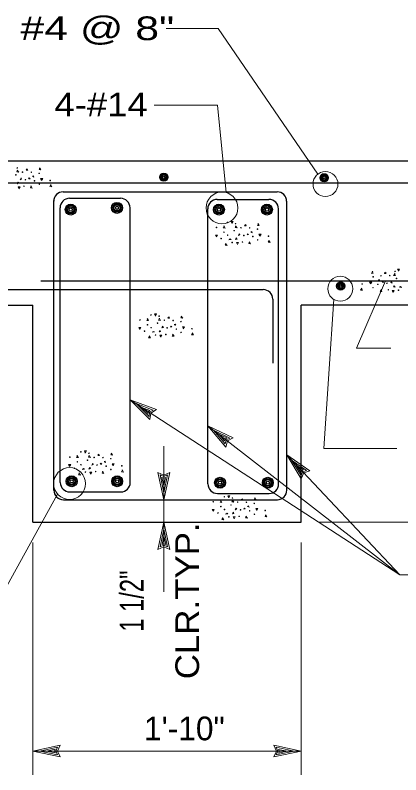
# Model space of a CAD drawing. Extents: x -28.1 to 13.9, y -16.1 to 13.9.
# Drawn here: x -17.081 to -15.047, y -12.729 to -8.723 of the extents above; entities that cross this region are included whole.
import ezdxf
from ezdxf.enums import TextEntityAlignment as Align

# ---------------------------------------------------------------- set-up
doc = ezdxf.new("R2010")
doc.units = 0
doc.header["$LTSCALE"] = 0.05
doc.layers.add('1', color=7, linetype='Continuous', lineweight=13)
doc.layers.add('2', color=7, linetype='Continuous', lineweight=13)

msp = doc.modelspace()

# ---------------------------------------------------------------- linework, layer by layer
at = {"layer": '1', "lineweight": 25}
for p, q in [((-18.82104, -9.49131), (-13.73804, -9.49131)), ((-18.82204, -9.60631), (-13.73904, -9.60631)), ((-16.82804, -9.65431), (-15.69904, -9.65431)), ((-16.79404, -9.68831), (-16.52504, -9.68831)), ((-16.01504, -9.69431), (-15.74204, -9.69431)), ((-16.87704, -11.22831), (-16.87704, -9.70031)), ((-15.64804, -11.22831), (-15.64804, -9.70431)), ((-16.84304, -11.18731), (-16.84304, -9.73831)), ((-16.47404, -11.18731), (-16.47404, -9.73831)), ((-16.06404, -11.19531), (-16.06404, -9.74431)), ((-15.69104, -11.19531), (-15.69104, -9.74431)), ((-16.94504, -10.12331), (-13.73804, -10.12331)), ((-18.81504, -10.17031), (-15.77204, -10.17031)), ((-18.82204, -10.25231), (-16.98804, -10.25231)), ((-16.98804, -11.39631), (-16.98804, -10.25231)), ((-15.72204, -10.22031), (-15.72204, -10.55831)), ((-15.57304, -11.39631), (-15.57304, -10.25231)), ((-13.73804, -10.25231), (-15.57304, -10.25231)), ((-16.79304, -11.23731), (-16.52404, -11.23731)), ((-16.01404, -11.24531), (-15.74104, -11.24531)), ((-16.82704, -11.27831), (-15.69804, -11.27831)), ((-16.98804, -11.39631), (-15.57304, -11.39631))]:
    msp.add_line(p, q, dxfattribs=at)
at = {"layer": '1'}
for p, q in [((-15.28104, -10.47831), (-15.12804, -10.12331)), ((-15.45204, -11.00831), (-15.40004, -10.22131)), ((-15.28104, -10.47831), (-15.10004, -10.47831)), ((-15.05104, -11.67531), (-16.47404, -10.75131)), ((-16.47404, -10.75131), (-16.33604, -10.80331)), ((-16.47404, -10.75131), (-16.37004, -10.85531)), ((-16.44304, -10.77131), (-16.35304, -10.80631)), ((-16.44304, -10.77131), (-16.37504, -10.83931)), ((-16.41304, -10.79131), (-16.38004, -10.82331)), ((-16.41304, -10.79131), (-16.37004, -10.80731)), ((-16.37804, -10.81331), (-16.38004, -10.82331)), ((-16.37004, -10.80731), (-16.37804, -10.81331)), ((-16.37204, -10.81731), (-16.37504, -10.83931)), ((-16.35304, -10.80631), (-16.37204, -10.81731)), ((-15.05104, -11.67531), (-16.06404, -10.88831)), ((-16.06404, -10.88831), (-15.93104, -10.95231)), ((-16.06404, -10.88831), (-15.96904, -11.00131)), ((-16.03504, -10.91131), (-15.94804, -10.95331)), ((-16.03504, -10.91131), (-15.97304, -10.98431)), ((-16.00604, -10.93331), (-15.97604, -10.96831)), ((-16.00604, -10.93331), (-15.96504, -10.95231)), ((-15.97404, -10.95831), (-15.97604, -10.96831)), ((-15.96504, -10.95231), (-15.97404, -10.95831)), ((-15.96804, -10.96331), (-15.97304, -10.98431)), ((-15.94804, -10.95331), (-15.96804, -10.96331)), ((-15.45204, -11.00831), (-15.06804, -11.00831)), ((-15.05104, -11.67531), (-15.64804, -11.04231)), ((-15.64804, -11.04231), (-15.52704, -11.12531)), ((-15.64804, -11.04231), (-15.57204, -11.16831)), ((-15.62304, -11.06931), (-15.54404, -11.12431)), ((-15.62304, -11.06931), (-15.57304, -11.15131)), ((-15.59804, -11.09531), (-15.57404, -11.13431)), ((-15.59804, -11.09531), (-15.56004, -11.12131)), ((-16.29704, -11.27831), (-16.32804, -11.13431)), ((-16.29704, -11.27831), (-16.26604, -11.13431)), ((-15.57004, -11.12531), (-15.57404, -11.13431)), ((-15.56404, -11.13131), (-15.57304, -11.15131)), ((-15.56004, -11.12131), (-15.57004, -11.12531)), ((-15.54404, -11.12431), (-15.56404, -11.13131)), ((-16.29704, -11.24131), (-16.31704, -11.14731)), ((-16.31704, -11.14731), (-16.29704, -11.15631)), ((-16.29704, -11.20531), (-16.30704, -11.16031)), ((-16.30704, -11.16031), (-16.29704, -11.16431)), ((-16.29704, -11.24131), (-16.27704, -11.14731)), ((-16.29704, -11.15631), (-16.27704, -11.14731)), ((-16.29704, -11.20531), (-16.28804, -11.16031)), ((-16.29704, -11.16431), (-16.28804, -11.16031)), ((-17.20904, -11.88431), (-16.85704, -11.24831)), ((-16.29704, -11.39631), (-16.32804, -11.54031)), ((-16.29704, -11.39631), (-16.26604, -11.54031)), ((-15.47804, -11.39631), (-11.56504, -11.39631)), ((-16.29704, -11.43331), (-16.31704, -11.52731)), ((-16.29704, -11.43331), (-16.27704, -11.52731)), ((-16.29704, -11.46931), (-16.30604, -11.51431)), ((-16.29704, -11.46931), (-16.28704, -11.51431)), ((-16.98804, -11.50431), (-16.98804, -12.72931)), ((-16.29704, -11.51831), (-16.31704, -11.52731)), ((-16.29704, -11.51031), (-16.30604, -11.51431)), ((-16.28704, -11.51431), (-16.29704, -11.51031)), ((-16.27704, -11.52731), (-16.29704, -11.51831)), ((-15.57304, -11.50431), (-15.57304, -12.72931)), ((-15.05104, -11.67531), (-14.66204, -11.67531)), ((-16.98804, -12.60431), (-16.84404, -12.57331)), ((-15.57304, -12.60431), (-15.71704, -12.57331)), ((-16.98804, -12.60431), (-15.57304, -12.60431)), ((-16.98804, -12.60431), (-16.84404, -12.63531)), ((-16.95104, -12.60431), (-16.85704, -12.58431)), ((-16.95104, -12.60431), (-16.85704, -12.62431)), ((-16.91504, -12.60431), (-16.87004, -12.59431)), ((-16.91504, -12.60431), (-16.87004, -12.61331)), ((-16.87004, -12.59431), (-16.87404, -12.60431)), ((-16.87404, -12.60431), (-16.87004, -12.61331)), ((-16.85704, -12.58431), (-16.86604, -12.60431)), ((-16.86604, -12.60431), (-16.85704, -12.62431)), ((-15.57304, -12.60431), (-15.71704, -12.63531)), ((-15.61004, -12.60431), (-15.70404, -12.58431)), ((-15.69504, -12.60431), (-15.70404, -12.58431)), ((-15.61004, -12.60431), (-15.70404, -12.62431)), ((-15.70404, -12.62431), (-15.69504, -12.60431)), ((-15.64604, -12.60431), (-15.69104, -12.59531)), ((-15.68704, -12.60431), (-15.69104, -12.59531)), ((-15.64604, -12.60431), (-15.69104, -12.61431)), ((-15.69104, -12.61431), (-15.68704, -12.60431))]:
    msp.add_line(p, q, dxfattribs=at)
for points in [[(-16.28404, -8.79231), (-16.01104, -8.79231), (-15.48504, -9.56131)], [(-16.34804, -9.19731), (-16.01404, -9.19731), (-15.96804, -9.65831)], [(-16.33604, -10.80331), (-16.36504, -10.82231), (-16.37004, -10.85531)], [(-15.93104, -10.95231), (-15.96104, -10.96831), (-15.96904, -11.00131)], [(-16.29704, -11.76431), (-16.29704, -11.39631), (-16.29704, -11.27831), (-16.29704, -10.99531)], [(-16.32804, -11.13431), (-16.29704, -11.14831), (-16.26604, -11.13431)], [(-15.52704, -11.12531), (-15.55904, -11.13731), (-15.57204, -11.16831)], [(-16.26604, -11.54031), (-16.29704, -11.52631), (-16.32804, -11.54031)], [(-16.84404, -12.57331), (-16.85804, -12.60431), (-16.84404, -12.63531)], [(-15.71704, -12.63531), (-15.70304, -12.60431), (-15.71704, -12.57331)]]:
    msp.add_lwpolyline(points, dxfattribs=at)
at = {"layer": '1', "lineweight": 25}
for centre, radius in [((-16.29699, -9.57723), 0.02168), ((-16.29699, -9.57723), 0.01681), ((-16.29699, -9.57723), 0.01233), ((-16.29699, -9.57723), 0.00623), ((-15.45099, -9.58023), 0.02168), ((-15.45099, -9.58023), 0.01681), ((-15.45099, -9.58023), 0.01233), ((-15.45099, -9.58023), 0.00623), ((-16.7881, -9.74788), 0.02891), ((-16.7881, -9.74788), 0.02242), ((-16.7881, -9.74788), 0.01644), ((-16.5441, -9.73888), 0.02891), ((-16.5441, -9.73888), 0.02242), ((-16.5441, -9.73888), 0.01644), ((-16.5441, -9.73888), 0.0083), ((-16.0061, -9.74788), 0.02891), ((-16.0061, -9.74788), 0.02242), ((-16.0061, -9.74788), 0.01644), ((-15.7531, -9.74788), 0.02891), ((-15.7531, -9.74788), 0.02242), ((-15.7531, -9.74788), 0.01644), ((-16.7881, -9.74788), 0.0083), ((-16.0061, -9.74788), 0.0083), ((-15.7531, -9.74788), 0.0083), ((-15.36399, -10.15123), 0.02168), ((-15.36399, -10.15123), 0.01681), ((-15.36399, -10.15123), 0.01233), ((-15.36399, -10.15123), 0.00623), ((-16.7831, -11.18088), 0.02891), ((-16.7831, -11.18088), 0.02242), ((-16.7831, -11.18088), 0.01644), ((-16.7831, -11.18088), 0.0083), ((-16.5431, -11.18088), 0.02891), ((-16.5431, -11.18088), 0.02242), ((-16.5431, -11.18088), 0.01644), ((-16.5431, -11.18088), 0.0083), ((-16.0001, -11.18887), 0.02891), ((-16.0001, -11.18887), 0.02242), ((-16.0001, -11.18887), 0.01644), ((-15.7481, -11.18887), 0.02891), ((-15.7481, -11.18887), 0.02242), ((-15.7481, -11.18887), 0.01644), ((-16.0001, -11.18887), 0.0083), ((-15.7481, -11.18887), 0.0083)]:
    msp.add_circle(centre, radius, dxfattribs=at)
at = {"layer": '1'}
for centre, radius in [((-15.44404, -9.61331), 0.0658), ((-15.99004, -9.73931), 0.0841), ((-15.36604, -10.16531), 0.0658), ((-16.79404, -11.19331), 0.0841)]:
    msp.add_circle(centre, radius, dxfattribs=at)
at = {"layer": '1', "lineweight": 25}
for centre, start, end in [((-16.82804, -9.70431), 90, 180), ((-15.69904, -9.70431), 0, 90), ((-16.79404, -9.73831), 90, 180), ((-16.52504, -9.73831), 0, 90), ((-16.01504, -9.74431), 90, 180), ((-15.74204, -9.74431), 0, 90), ((-15.77204, -10.22031), 0, 90), ((-16.79304, -11.18731), 180, 270), ((-16.52404, -11.18731), 270, 0), ((-16.01404, -11.19531), 180, 270), ((-15.74104, -11.19531), 270, 0), ((-16.82704, -11.22831), 180, 270), ((-15.69804, -11.22831), 270, 0)]:
    msp.add_arc(centre, 0.05, start, end, dxfattribs=at)
at = {"layer": '2'}
for p, q in [((-17.02304, -9.53731), (-17.01704, -9.53231)), ((-15.87104, -9.83131), (-15.86504, -9.82631)), ((-15.12404, -10.08331), (-15.13004, -10.07831)), ((-16.27504, -10.31931), (-16.26904, -10.31431)), ((-16.64504, -11.04231), (-16.63904, -11.03731)), ((-15.88804, -11.27831), (-15.88204, -11.27331))]:
    msp.add_line(p, q, dxfattribs=at)
for points in [[(-17.01704, -9.53231), (-17.01504, -9.53931), (-17.02304, -9.53931)], [(-16.95004, -9.52731), (-16.95504, -9.53731), (-16.94504, -9.53831), (-16.95304, -9.52731)], [(-17.06804, -9.53931), (-17.07304, -9.54931), (-17.06204, -9.55031), (-17.07004, -9.53931)], [(-16.99004, -9.57231), (-16.98504, -9.57031), (-16.98204, -9.57631), (-16.99004, -9.57331)], [(-17.01004, -9.58531), (-17.00704, -9.58131), (-17.00204, -9.58531), (-17.00904, -9.58631)], [(-16.94204, -9.59231), (-16.94704, -9.58431), (-16.93604, -9.58431), (-16.94204, -9.59431)], [(-17.06104, -9.63731), (-17.06604, -9.62831), (-17.05504, -9.62831), (-17.06104, -9.63831)], [(-16.99604, -9.62331), (-17.00104, -9.63331), (-16.99104, -9.63431), (-16.99904, -9.62331)], [(-16.89304, -9.61631), (-16.89804, -9.62631), (-16.88804, -9.62731), (-16.89504, -9.61631)], [(-15.93704, -9.81931), (-15.94204, -9.81031), (-15.93104, -9.81031), (-15.93704, -9.82131)], [(-15.97804, -9.83431), (-15.98304, -9.84431), (-15.97304, -9.84531), (-15.98104, -9.83431)], [(-15.91604, -9.83331), (-15.92104, -9.84331), (-15.91004, -9.84431), (-15.91804, -9.83331)], [(-15.86504, -9.82631), (-15.86304, -9.83331), (-15.87104, -9.83331)], [(-15.79804, -9.82131), (-15.80304, -9.83131), (-15.79304, -9.83231), (-15.80104, -9.82131)], [(-16.02004, -9.89031), (-16.02504, -9.88231), (-16.01404, -9.88231), (-16.02004, -9.89231)], [(-15.85804, -9.87931), (-15.85504, -9.87531), (-15.85004, -9.87931), (-15.85704, -9.88031)], [(-15.83804, -9.86631), (-15.83304, -9.86431), (-15.83004, -9.87031), (-15.83804, -9.86731)], [(-15.79004, -9.88631), (-15.79504, -9.87831), (-15.78404, -9.87831), (-15.79004, -9.88831)], [(-15.96804, -9.92631), (-15.97304, -9.93631), (-15.96304, -9.93731), (-15.97104, -9.92631)], [(-15.95104, -9.90531), (-15.94604, -9.90231), (-15.94204, -9.90531), (-15.95404, -9.90731)], [(-15.90904, -9.93131), (-15.91404, -9.92231), (-15.90304, -9.92231), (-15.90904, -9.93231)], [(-15.84404, -9.91731), (-15.84904, -9.92731), (-15.83904, -9.92831), (-15.84704, -9.91731)], [(-15.74104, -9.91031), (-15.74604, -9.92031), (-15.73604, -9.92131), (-15.74304, -9.91031)], [(-15.19704, -10.07331), (-15.19204, -10.08331), (-15.20204, -10.08431), (-15.19404, -10.07331)], [(-15.13004, -10.07831), (-15.13204, -10.08531), (-15.12404, -10.08531)], [(-15.07904, -10.08531), (-15.07404, -10.09531), (-15.08504, -10.09631), (-15.07704, -10.08531)], [(-15.05804, -10.07131), (-15.05304, -10.06231), (-15.06404, -10.06231), (-15.05804, -10.07331)], [(-15.20504, -10.13831), (-15.20004, -10.13031), (-15.21104, -10.13031), (-15.20504, -10.14031)], [(-15.15704, -10.11831), (-15.16204, -10.11631), (-15.16504, -10.12231), (-15.15704, -10.11931)], [(-15.13704, -10.13131), (-15.14004, -10.12731), (-15.14504, -10.13131), (-15.13804, -10.13231)], [(-15.25404, -10.16231), (-15.24904, -10.17231), (-15.25904, -10.17331), (-15.25204, -10.16231)], [(-15.15104, -10.16931), (-15.14604, -10.17931), (-15.15604, -10.18031), (-15.14804, -10.16931)], [(-15.08604, -10.18331), (-15.08104, -10.17431), (-15.09204, -10.17431), (-15.08604, -10.18431)], [(-15.04404, -10.15731), (-15.04904, -10.15431), (-15.05304, -10.15731), (-15.04104, -10.15931)], [(-16.38204, -10.32231), (-16.38704, -10.33231), (-16.37704, -10.33331), (-16.38504, -10.32231)], [(-16.34104, -10.30731), (-16.34604, -10.29831), (-16.33504, -10.29831), (-16.34104, -10.30931)], [(-16.32004, -10.32131), (-16.32504, -10.33131), (-16.31404, -10.33231), (-16.32204, -10.32131)], [(-16.26904, -10.31431), (-16.26704, -10.32131), (-16.27504, -10.32131)], [(-16.20204, -10.30931), (-16.20704, -10.31931), (-16.19704, -10.32031), (-16.20504, -10.30931)], [(-16.42404, -10.37831), (-16.42904, -10.37031), (-16.41804, -10.37031), (-16.42404, -10.38031)], [(-16.26204, -10.36731), (-16.25904, -10.36331), (-16.25404, -10.36731), (-16.26104, -10.36831)], [(-16.24204, -10.35431), (-16.23704, -10.35231), (-16.23404, -10.35831), (-16.24204, -10.35531)], [(-16.19404, -10.37431), (-16.19904, -10.36631), (-16.18804, -10.36631), (-16.19404, -10.37631)], [(-16.37204, -10.41431), (-16.37704, -10.42431), (-16.36704, -10.42531), (-16.37504, -10.41431)], [(-16.35504, -10.39331), (-16.35004, -10.39031), (-16.34604, -10.39331), (-16.35804, -10.39531)], [(-16.31304, -10.41931), (-16.31804, -10.41031), (-16.30704, -10.41031), (-16.31304, -10.42031)], [(-16.24804, -10.40531), (-16.25304, -10.41531), (-16.24304, -10.41631), (-16.25104, -10.40531)], [(-16.14504, -10.39831), (-16.15004, -10.40831), (-16.14004, -10.40931), (-16.14704, -10.39831)], [(-16.75204, -11.04531), (-16.75704, -11.05531), (-16.74704, -11.05631), (-16.75504, -11.04531)], [(-16.71104, -11.03031), (-16.71604, -11.02131), (-16.70504, -11.02131), (-16.71104, -11.03231)], [(-16.69004, -11.04431), (-16.69504, -11.05431), (-16.68404, -11.05531), (-16.69204, -11.04431)], [(-16.63904, -11.03731), (-16.63704, -11.04431), (-16.64504, -11.04431)], [(-16.57204, -11.03231), (-16.57704, -11.04231), (-16.56704, -11.04331), (-16.57504, -11.03231)], [(-16.79404, -11.10131), (-16.79904, -11.09331), (-16.78804, -11.09331), (-16.79404, -11.10331)], [(-16.63204, -11.09031), (-16.62904, -11.08631), (-16.62404, -11.09031), (-16.63104, -11.09131)], [(-16.61204, -11.07731), (-16.60704, -11.07531), (-16.60404, -11.08131), (-16.61204, -11.07831)], [(-16.56404, -11.09731), (-16.56904, -11.08931), (-16.55804, -11.08931), (-16.56404, -11.09931)], [(-16.74204, -11.13731), (-16.74704, -11.14731), (-16.73704, -11.14831), (-16.74504, -11.13731)], [(-16.72504, -11.11631), (-16.72004, -11.11331), (-16.71604, -11.11631), (-16.72804, -11.11831)], [(-16.68304, -11.14231), (-16.68804, -11.13331), (-16.67704, -11.13331), (-16.68304, -11.14331)], [(-16.61804, -11.12831), (-16.62304, -11.13831), (-16.61304, -11.13931), (-16.62104, -11.12831)], [(-16.51504, -11.12131), (-16.52004, -11.13131), (-16.51004, -11.13231), (-16.51704, -11.12131)], [(-15.95404, -11.26631), (-15.95904, -11.25731), (-15.94804, -11.25731), (-15.95404, -11.26831)], [(-15.99504, -11.28131), (-16.00004, -11.29131), (-15.99004, -11.29231), (-15.99804, -11.28131)], [(-15.93304, -11.28031), (-15.93804, -11.29031), (-15.92704, -11.29131), (-15.93504, -11.28031)], [(-15.88204, -11.27331), (-15.88004, -11.28031), (-15.88804, -11.28031)], [(-15.81504, -11.26831), (-15.82004, -11.27831), (-15.81004, -11.27931), (-15.81804, -11.26831)], [(-16.03704, -11.33731), (-16.04204, -11.32931), (-16.03104, -11.32931), (-16.03704, -11.33931)], [(-15.87504, -11.32631), (-15.87204, -11.32231), (-15.86704, -11.32631), (-15.87404, -11.32731)], [(-15.85504, -11.31331), (-15.85004, -11.31131), (-15.84704, -11.31731), (-15.85504, -11.31431)], [(-15.80704, -11.33331), (-15.81204, -11.32531), (-15.80104, -11.32531), (-15.80704, -11.33531)], [(-15.98504, -11.37331), (-15.99004, -11.38331), (-15.98004, -11.38431), (-15.98804, -11.37331)], [(-15.96804, -11.35231), (-15.96304, -11.34931), (-15.95904, -11.35231), (-15.97104, -11.35431)], [(-15.92604, -11.37831), (-15.93104, -11.36931), (-15.92004, -11.36931), (-15.92604, -11.37931)], [(-15.86104, -11.36431), (-15.86604, -11.37431), (-15.85604, -11.37531), (-15.86404, -11.36431)], [(-15.75804, -11.35731), (-15.76304, -11.36731), (-15.75304, -11.36831), (-15.76004, -11.35731)]]:
    msp.add_lwpolyline(points, dxfattribs=at)
for points in [[(-17.07004, -9.61131), (-17.06504, -9.60331), (-17.06204, -9.60931)], [(-17.05504, -9.59031), (-17.05004, -9.58131), (-17.04704, -9.58731)], [(-15.90304, -9.88431), (-15.89804, -9.87531), (-15.89504, -9.88131)], [(-15.91804, -9.90531), (-15.91304, -9.89731), (-15.91004, -9.90331)], [(-15.09204, -10.13631), (-15.09704, -10.12731), (-15.10004, -10.13331)], [(-15.07704, -10.15731), (-15.08204, -10.14931), (-15.08504, -10.15531)], [(-16.30704, -10.37231), (-16.30204, -10.36331), (-16.29904, -10.36931)], [(-16.32204, -10.39331), (-16.31704, -10.38531), (-16.31404, -10.39131)], [(-16.67704, -11.09531), (-16.67204, -11.08631), (-16.66904, -11.09231)], [(-16.69204, -11.11631), (-16.68704, -11.10831), (-16.68404, -11.11431)], [(-15.92004, -11.33131), (-15.91504, -11.32231), (-15.91204, -11.32831)], [(-15.93504, -11.35231), (-15.93004, -11.34431), (-15.92704, -11.35031)]]:
    msp.add_lwpolyline(points, close=True, dxfattribs=at)
for centre in [(-17.07004, -9.52819), (-17.07754, -9.56519), (-17.04229, -9.54994), (-16.99604, -9.55094), (-16.95479, -9.55669), (-17.02704, -9.59044), (-16.97904, -9.59619), (-16.95379, -9.61394), (-16.89654, -9.59444), (-17.03454, -9.62494), (-15.96079, -9.81544), (-16.01904, -9.84219), (-15.91804, -9.82219), (-15.89029, -9.84394), (-15.84404, -9.84494), (-15.80279, -9.85069), (-15.97929, -9.86744), (-15.96004, -9.88269), (-15.92554, -9.85919), (-15.87504, -9.88444), (-15.82704, -9.89019), (-15.74454, -9.88844), (-15.99454, -9.90119), (-15.93654, -9.92144), (-15.88254, -9.91894), (-15.80179, -9.90794), (-15.15104, -10.09694), (-15.10479, -10.09594), (-15.07704, -10.07419), (-15.19229, -10.10269), (-15.12004, -10.13644), (-15.06954, -10.11119), (-15.25054, -10.14044), (-15.19329, -10.15994), (-15.16804, -10.14219), (-15.11254, -10.17094), (-15.05854, -10.17344), (-16.42304, -10.33019), (-16.36479, -10.30344), (-16.32204, -10.31019), (-16.29429, -10.33194), (-16.24804, -10.33294), (-16.20679, -10.33869), (-16.38329, -10.35544), (-16.36404, -10.37069), (-16.32954, -10.34719), (-16.27904, -10.37244), (-16.23104, -10.37819), (-16.14854, -10.37644), (-16.39854, -10.38919), (-16.34054, -10.40944), (-16.28654, -10.40694), (-16.20579, -10.39594), (-16.79304, -11.05319), (-16.73479, -11.02644), (-16.69204, -11.03319), (-16.66429, -11.05494), (-16.61804, -11.05594), (-16.75329, -11.07844), (-16.73404, -11.09369), (-16.69954, -11.07019), (-16.64904, -11.09544), (-16.57679, -11.06169), (-16.51854, -11.09944), (-16.76854, -11.11219), (-16.71054, -11.13244), (-16.65654, -11.12994), (-16.60104, -11.10119), (-16.57579, -11.11894), (-16.03604, -11.28919), (-15.97779, -11.26244), (-15.93504, -11.26919), (-15.90729, -11.29094), (-15.86104, -11.29194), (-15.81979, -11.29769), (-15.99629, -11.31444), (-15.97704, -11.32969), (-15.94254, -11.30619), (-15.89204, -11.33144), (-15.84404, -11.33719), (-15.76154, -11.33544), (-16.01154, -11.34819), (-15.95354, -11.36844), (-15.89954, -11.36594), (-15.81879, -11.35494)]:
    msp.add_circle(centre, 0.00162, dxfattribs=at)

# ---------------------------------------------------------------- texts
at = {"layer": '1'}
for s, width, p in [('#4 @ 8"', 1.35, (-17.05304, -8.85431)), ('4-#14', 1.15, (-16.87404, -9.25631))]:
    msp.add_text(s, height=0.125, dxfattribs=dict(at, width=width)).set_placement(p)
at = {"layer": '1', "width": 1.1}
msp.add_text('CLR.TYP.', height=0.125, rotation=90, dxfattribs=at).set_placement((-16.11104, -11.81152), align=Align.CENTER)
at = {"layer": '1', "width": 0.75}
msp.add_text('1 1/2"', height=0.125, rotation=90, dxfattribs=at).set_placement((-16.40404, -11.65158), align=Align.RIGHT)
at = {"layer": '1'}
msp.add_text('1\'-10"', height=0.125, dxfattribs=at).set_placement((-16.18833, -12.54731), align=Align.CENTER)

doc.saveas('drawing.dxf')
